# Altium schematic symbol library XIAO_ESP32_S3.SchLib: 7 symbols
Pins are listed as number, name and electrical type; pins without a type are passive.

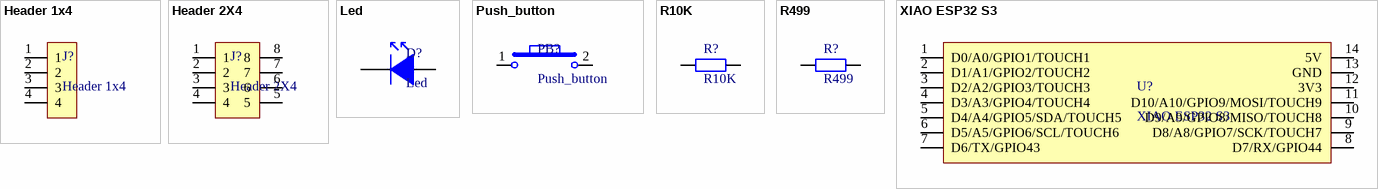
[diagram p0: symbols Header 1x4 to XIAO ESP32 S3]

## Header 1x4
designator J?
footprint HDR4X1_FEMALE
pins: 1, 2, 3, 4

## Header 2X4
designator J?
footprint HDR4X2_FEMALE
pins: 1, 2, 3, 4, 5, 6, 7, 8

## Led
designator D?
1206
footprint LED1206
pins: 1, 2

## Push_button
designator PB?
PTS636SM25FSMTR LFS
footprint 6x3x2.5mm SMD
pins: 1, 2

## R10K
designator R?
footprint RES1206
pins: 1, 2

## R499
designator R?
footprint RES1206
pins: 1, 2

## XIAO ESP32 S3
designator U?
footprint XIAO_ESP32_S3
pins: 1 D0/A0/GPIO1/TOUCH1, 2 D1/A1/GPIO2/TOUCH2, 3 D2/A2/GPIO3/TOUCH3, 4 D3/A3/GPIO4/TOUCH4, 5 D4/A4/GPIO5/SDA/TOUCH5, 6 D5/A5/GPIO6/SCL/TOUCH6, 7 D6/TX/GPIO43, 8 D7/RX/GPIO44, 9 D8/A8/GPIO7/SCK/TOUCH7, 10 D9/A9/GPIO8/MISO/TOUCH8, 11 D10/A10/GPIO9/MOSI/TOUCH9, 12 3V3, 13 GND, 14 5V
